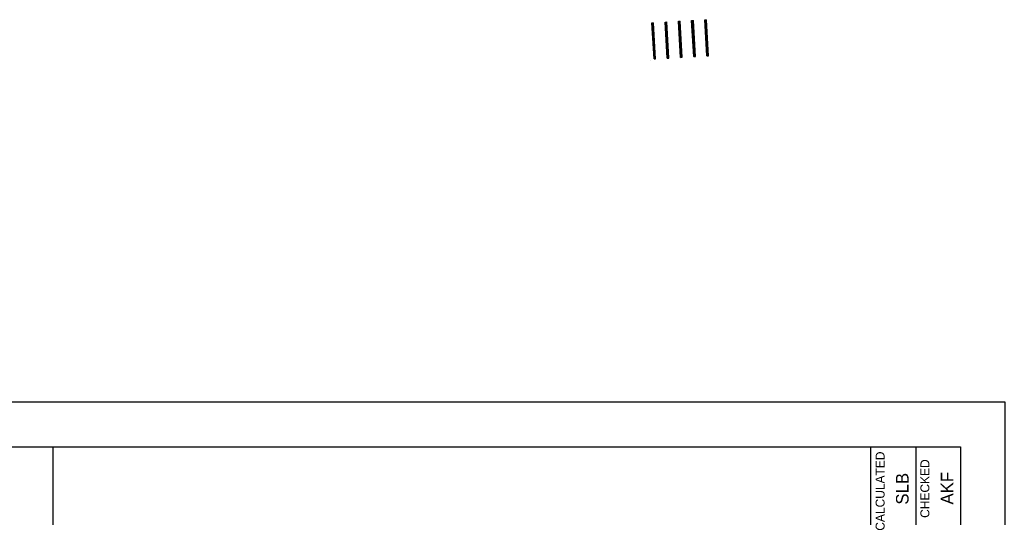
# Model space of a CAD drawing. Extents: x 1822205 to 1824724, y 710141 to 711863.
# Drawn here: x 1823491 to 1824041, y 711177 to 711455 of the extents above; entities that cross this region are included whole.
import ezdxf

# ---------------------------------------------------------------- set-up
doc = ezdxf.new("R2010")
doc.units = 0
for name, color, linetype in [('PM_P_Cells', 7, 'Continuous'), ('SH_Border', 7, 'Continuous'), ('SH_Cut_Line', 7, 'Continuous'), ('SH_Data', 7, 'Continuous')]:
    doc.layers.add(name, color=color, linetype=linetype)

msp = doc.modelspace()

# ---------------------------------------------------------------- linework, layer by layer
at = {"layer": 'PM_P_Cells'}
msp.add_line((1823509.74, 711216.46), (1823509.74, 710166.46), dxfattribs=at)
at = {"layer": 'SH_Border'}
for p, q in [((1823966.39, 710166.46), (1823966.39, 711216.46)), ((1823991.39, 711216.46), (1823991.39, 711166.46))]:
    msp.add_line(p, q, dxfattribs=at)
msp.add_lwpolyline([(1822441.39, 711216.46), (1824016.39, 711216.46), (1824016.39, 710166.46), (1822441.39, 710166.46)], close=True, dxfattribs=at)
at = {"layer": 'SH_Cut_Line'}
msp.add_lwpolyline([(1822341.39, 710141.46), (1824041.39, 710141.46), (1824041.39, 711241.46), (1822341.39, 711241.46)], close=True, dxfattribs=at)
at = {"layer": 'SH_Data'}
for p, q in [((1823844.17, 711453.19), (1823845.07, 711453.24)), ((1823845.3, 711433.06), (1823844.17, 711453.19)), ((1823844.19, 711452.91), (1823845.08, 711452.96)), ((1823846.2, 711433.11), (1823845.07, 711453.24)), ((1823851.5, 711453.6), (1823852.48, 711453.65)), ((1823852.63, 711433.47), (1823851.5, 711453.6)), ((1823851.51, 711453.32), (1823852.49, 711453.37)), ((1823851.53, 711453.04), (1823852.51, 711453.09)), ((1823853.6, 711433.52), (1823852.48, 711453.65)), ((1823858.91, 711454.01), (1823859.89, 711454.07)), ((1823860.03, 711433.88), (1823858.91, 711454.01)), ((1823858.92, 711453.73), (1823859.9, 711453.79)), ((1823858.94, 711453.45), (1823859.92, 711453.51)), ((1823858.95, 711453.17), (1823859.93, 711453.23)), ((1823858.97, 711452.89), (1823859.95, 711452.95)), ((1823861.01, 711433.94), (1823859.89, 711454.07)), ((1823866.32, 711454.43), (1823867.29, 711454.48)), ((1823867.44, 711434.3), (1823866.32, 711454.43)), ((1823866.33, 711454.15), (1823867.31, 711454.2)), ((1823866.35, 711453.87), (1823867.33, 711453.92)), ((1823866.36, 711453.59), (1823867.34, 711453.64)), ((1823866.38, 711453.31), (1823867.36, 711453.36)), ((1823866.39, 711453.03), (1823867.37, 711453.08)), ((1823868.42, 711434.35), (1823867.29, 711454.48)), ((1823873.72, 711454.84), (1823874.62, 711454.89)), ((1823874.85, 711434.71), (1823873.72, 711454.84)), ((1823873.74, 711454.56), (1823874.64, 711454.61)), ((1823873.76, 711454.28), (1823874.65, 711454.33)), ((1823873.77, 711454), (1823874.67, 711454.05)), ((1823873.79, 711453.72), (1823874.69, 711453.77)), ((1823873.8, 711453.44), (1823874.7, 711453.49)), ((1823873.82, 711453.16), (1823874.72, 711453.21)), ((1823873.83, 711452.88), (1823874.73, 711452.93)), ((1823875.75, 711434.76), (1823874.62, 711454.89)), ((1823844.2, 711452.63), (1823845.1, 711452.68)), ((1823844.22, 711452.35), (1823845.12, 711452.4)), ((1823844.23, 711452.07), (1823845.13, 711452.12)), ((1823844.25, 711451.79), (1823845.15, 711451.84)), ((1823844.26, 711451.51), (1823845.16, 711451.56)), ((1823844.28, 711451.23), (1823845.18, 711451.28)), ((1823844.3, 711450.95), (1823845.19, 711451)), ((1823844.31, 711450.67), (1823845.21, 711450.72)), ((1823844.33, 711450.39), (1823845.23, 711450.44)), ((1823844.34, 711450.11), (1823845.24, 711450.16)), ((1823844.36, 711449.83), (1823845.26, 711449.88)), ((1823844.37, 711449.55), (1823845.27, 711449.6)), ((1823844.39, 711449.27), (1823845.29, 711449.32)), ((1823844.41, 711448.99), (1823845.3, 711449.04)), ((1823844.42, 711448.71), (1823845.32, 711448.76)), ((1823844.44, 711448.43), (1823845.34, 711448.48)), ((1823844.45, 711448.15), (1823845.35, 711448.2)), ((1823844.47, 711447.87), (1823845.37, 711447.92)), ((1823844.48, 711447.59), (1823845.38, 711447.64)), ((1823844.5, 711447.31), (1823845.4, 711447.36)), ((1823851.55, 711452.76), (1823852.52, 711452.81)), ((1823851.56, 711452.48), (1823852.54, 711452.53)), ((1823851.58, 711452.2), (1823852.56, 711452.25)), ((1823851.59, 711451.92), (1823852.57, 711451.97)), ((1823851.61, 711451.64), (1823852.59, 711451.69)), ((1823851.62, 711451.36), (1823852.6, 711451.41)), ((1823851.64, 711451.08), (1823852.62, 711451.13)), ((1823851.66, 711450.8), (1823852.63, 711450.85)), ((1823851.67, 711450.52), (1823852.65, 711450.58)), ((1823851.69, 711450.24), (1823852.67, 711450.3)), ((1823851.7, 711449.96), (1823852.68, 711450.02)), ((1823851.72, 711449.68), (1823852.7, 711449.74)), ((1823851.73, 711449.4), (1823852.71, 711449.46)), ((1823851.75, 711449.12), (1823852.73, 711449.18)), ((1823851.77, 711448.84), (1823852.74, 711448.9)), ((1823851.78, 711448.56), (1823852.76, 711448.62)), ((1823851.8, 711448.28), (1823852.77, 711448.34)), ((1823851.81, 711448), (1823852.79, 711448.06)), ((1823851.83, 711447.72), (1823852.81, 711447.78)), ((1823851.84, 711447.45), (1823852.82, 711447.5)), ((1823858.99, 711452.61), (1823859.96, 711452.67)), ((1823859, 711452.33), (1823859.98, 711452.39)), ((1823859.02, 711452.05), (1823860, 711452.11)), ((1823859.03, 711451.77), (1823860.01, 711451.83)), ((1823859.05, 711451.49), (1823860.03, 711451.55)), ((1823859.06, 711451.22), (1823860.04, 711451.27)), ((1823859.08, 711450.94), (1823860.06, 711450.99)), ((1823859.1, 711450.66), (1823860.07, 711450.71)), ((1823859.11, 711450.38), (1823860.09, 711450.43)), ((1823859.13, 711450.1), (1823860.11, 711450.15)), ((1823859.14, 711449.82), (1823860.12, 711449.87)), ((1823859.16, 711449.54), (1823860.14, 711449.59)), ((1823859.17, 711449.26), (1823860.15, 711449.31)), ((1823859.19, 711448.98), (1823860.17, 711449.03)), ((1823859.2, 711448.7), (1823860.18, 711448.75)), ((1823859.22, 711448.42), (1823860.2, 711448.47)), ((1823859.24, 711448.14), (1823860.21, 711448.19)), ((1823859.25, 711447.86), (1823860.23, 711447.92)), ((1823859.27, 711447.58), (1823860.25, 711447.64)), ((1823866.41, 711452.75), (1823867.39, 711452.8)), ((1823866.43, 711452.47), (1823867.4, 711452.52)), ((1823866.44, 711452.19), (1823867.42, 711452.24)), ((1823866.46, 711451.91), (1823867.44, 711451.96)), ((1823866.47, 711451.63), (1823867.45, 711451.68)), ((1823866.49, 711451.35), (1823867.47, 711451.41)), ((1823866.5, 711451.07), (1823867.48, 711451.13)), ((1823866.52, 711450.79), (1823867.5, 711450.85)), ((1823866.53, 711450.51), (1823867.51, 711450.57)), ((1823866.55, 711450.23), (1823867.53, 711450.29)), ((1823866.57, 711449.95), (1823867.54, 711450.01)), ((1823866.58, 711449.67), (1823867.56, 711449.73)), ((1823866.6, 711449.39), (1823867.58, 711449.45)), ((1823866.61, 711449.11), (1823867.59, 711449.17)), ((1823866.63, 711448.83), (1823867.61, 711448.89)), ((1823866.64, 711448.55), (1823867.62, 711448.61)), ((1823866.66, 711448.28), (1823867.64, 711448.33)), ((1823866.68, 711448), (1823867.65, 711448.05)), ((1823866.69, 711447.72), (1823867.67, 711447.77)), ((1823866.71, 711447.44), (1823867.69, 711447.49)), ((1823873.85, 711452.6), (1823874.75, 711452.65)), ((1823873.87, 711452.32), (1823874.76, 711452.37)), ((1823873.88, 711452.05), (1823874.78, 711452.1)), ((1823873.9, 711451.77), (1823874.79, 711451.82)), ((1823873.91, 711451.49), (1823874.81, 711451.54)), ((1823873.93, 711451.21), (1823874.83, 711451.26)), ((1823873.94, 711450.93), (1823874.84, 711450.98)), ((1823873.96, 711450.65), (1823874.86, 711450.7)), ((1823873.97, 711450.37), (1823874.87, 711450.42)), ((1823873.99, 711450.09), (1823874.89, 711450.14)), ((1823874.01, 711449.81), (1823874.9, 711449.86)), ((1823874.02, 711449.53), (1823874.92, 711449.58)), ((1823874.04, 711449.25), (1823874.94, 711449.3)), ((1823874.05, 711448.97), (1823874.95, 711449.02)), ((1823874.07, 711448.69), (1823874.97, 711448.74)), ((1823874.08, 711448.41), (1823874.98, 711448.46)), ((1823874.1, 711448.13), (1823875, 711448.18)), ((1823874.12, 711447.85), (1823875.01, 711447.9)), ((1823874.13, 711447.57), (1823875.03, 711447.62)), ((1823844.51, 711447.03), (1823845.41, 711447.09)), ((1823844.53, 711446.76), (1823845.43, 711446.81)), ((1823844.55, 711446.48), (1823845.44, 711446.53)), ((1823844.56, 711446.2), (1823845.46, 711446.25)), ((1823844.58, 711445.92), (1823845.48, 711445.97)), ((1823844.59, 711445.64), (1823845.49, 711445.69)), ((1823844.61, 711445.36), (1823845.51, 711445.41)), ((1823844.62, 711445.08), (1823845.52, 711445.13)), ((1823844.64, 711444.8), (1823845.54, 711444.85)), ((1823844.66, 711444.52), (1823845.55, 711444.57)), ((1823844.67, 711444.24), (1823845.57, 711444.29)), ((1823844.69, 711443.96), (1823845.59, 711444.01)), ((1823844.7, 711443.68), (1823845.6, 711443.73)), ((1823844.72, 711443.4), (1823845.62, 711443.45)), ((1823844.73, 711443.12), (1823845.63, 711443.17)), ((1823844.75, 711442.84), (1823845.65, 711442.89)), ((1823844.77, 711442.56), (1823845.66, 711442.61)), ((1823844.78, 711442.28), (1823845.68, 711442.33)), ((1823844.8, 711442), (1823845.7, 711442.05)), ((1823851.86, 711447.17), (1823852.84, 711447.22)), ((1823851.87, 711446.89), (1823852.85, 711446.94)), ((1823851.89, 711446.61), (1823852.87, 711446.66)), ((1823851.91, 711446.33), (1823852.88, 711446.38)), ((1823851.92, 711446.05), (1823852.9, 711446.1)), ((1823851.94, 711445.77), (1823852.92, 711445.82)), ((1823851.95, 711445.49), (1823852.93, 711445.54)), ((1823851.97, 711445.21), (1823852.95, 711445.26)), ((1823851.98, 711444.93), (1823852.96, 711444.98)), ((1823852, 711444.65), (1823852.98, 711444.7)), ((1823852.02, 711444.37), (1823852.99, 711444.43)), ((1823852.03, 711444.09), (1823853.01, 711444.15)), ((1823852.05, 711443.81), (1823853.03, 711443.87)), ((1823852.06, 711443.53), (1823853.04, 711443.59)), ((1823852.08, 711443.25), (1823853.06, 711443.31)), ((1823852.09, 711442.97), (1823853.07, 711443.03)), ((1823852.11, 711442.69), (1823853.09, 711442.75)), ((1823852.13, 711442.41), (1823853.1, 711442.47)), ((1823852.14, 711442.13), (1823853.12, 711442.19)), ((1823852.16, 711441.85), (1823853.14, 711441.91)), ((1823859.28, 711447.3), (1823860.26, 711447.36)), ((1823859.3, 711447.02), (1823860.28, 711447.08)), ((1823859.31, 711446.74), (1823860.29, 711446.8)), ((1823859.33, 711446.46), (1823860.31, 711446.52)), ((1823859.35, 711446.18), (1823860.32, 711446.24)), ((1823859.36, 711445.9), (1823860.34, 711445.96)), ((1823859.38, 711445.62), (1823860.36, 711445.68)), ((1823859.39, 711445.34), (1823860.37, 711445.4)), ((1823859.41, 711445.06), (1823860.39, 711445.12)), ((1823859.42, 711444.79), (1823860.4, 711444.84)), ((1823859.44, 711444.51), (1823860.42, 711444.56)), ((1823859.46, 711444.23), (1823860.43, 711444.28)), ((1823859.47, 711443.95), (1823860.45, 711444)), ((1823859.49, 711443.67), (1823860.47, 711443.72)), ((1823859.5, 711443.39), (1823860.48, 711443.44)), ((1823859.52, 711443.11), (1823860.5, 711443.16)), ((1823859.53, 711442.83), (1823860.51, 711442.88)), ((1823859.55, 711442.55), (1823860.53, 711442.6)), ((1823859.57, 711442.27), (1823860.54, 711442.32)), ((1823859.58, 711441.99), (1823860.56, 711442.04)), ((1823866.72, 711447.16), (1823867.7, 711447.21)), ((1823866.74, 711446.88), (1823867.72, 711446.93)), ((1823866.75, 711446.6), (1823867.73, 711446.65)), ((1823866.77, 711446.32), (1823867.75, 711446.37)), ((1823866.79, 711446.04), (1823867.76, 711446.09)), ((1823866.8, 711445.76), (1823867.78, 711445.81)), ((1823866.82, 711445.48), (1823867.8, 711445.53)), ((1823866.83, 711445.2), (1823867.81, 711445.25)), ((1823866.85, 711444.92), (1823867.83, 711444.98)), ((1823866.86, 711444.64), (1823867.84, 711444.7)), ((1823866.88, 711444.36), (1823867.86, 711444.42)), ((1823866.9, 711444.08), (1823867.87, 711444.14)), ((1823866.91, 711443.8), (1823867.89, 711443.86)), ((1823866.93, 711443.52), (1823867.9, 711443.58)), ((1823866.94, 711443.24), (1823867.92, 711443.3)), ((1823866.96, 711442.96), (1823867.94, 711443.02)), ((1823866.97, 711442.68), (1823867.95, 711442.74)), ((1823866.99, 711442.4), (1823867.97, 711442.46)), ((1823867, 711442.12), (1823867.98, 711442.18)), ((1823867.02, 711441.85), (1823868, 711441.9)), ((1823874.15, 711447.29), (1823875.05, 711447.34)), ((1823874.16, 711447.01), (1823875.06, 711447.06)), ((1823874.18, 711446.73), (1823875.08, 711446.78)), ((1823874.19, 711446.45), (1823875.09, 711446.5)), ((1823874.21, 711446.17), (1823875.11, 711446.22)), ((1823874.23, 711445.89), (1823875.12, 711445.94)), ((1823874.24, 711445.62), (1823875.14, 711445.67)), ((1823874.26, 711445.34), (1823875.16, 711445.39)), ((1823874.27, 711445.06), (1823875.17, 711445.11)), ((1823874.29, 711444.78), (1823875.19, 711444.83)), ((1823874.3, 711444.5), (1823875.2, 711444.55)), ((1823874.32, 711444.22), (1823875.22, 711444.27)), ((1823874.33, 711443.94), (1823875.23, 711443.99)), ((1823874.35, 711443.66), (1823875.25, 711443.71)), ((1823874.37, 711443.38), (1823875.26, 711443.43)), ((1823874.38, 711443.1), (1823875.28, 711443.15)), ((1823874.4, 711442.82), (1823875.3, 711442.87)), ((1823874.41, 711442.54), (1823875.31, 711442.59)), ((1823874.43, 711442.26), (1823875.33, 711442.31)), ((1823874.44, 711441.98), (1823875.34, 711442.03)), ((1823844.81, 711441.72), (1823845.71, 711441.77)), ((1823844.83, 711441.44), (1823845.73, 711441.49)), ((1823844.84, 711441.16), (1823845.74, 711441.21)), ((1823844.86, 711440.88), (1823845.76, 711440.93)), ((1823844.88, 711440.6), (1823845.77, 711440.66)), ((1823844.89, 711440.33), (1823845.79, 711440.38)), ((1823844.91, 711440.05), (1823845.81, 711440.1)), ((1823844.92, 711439.77), (1823845.82, 711439.82)), ((1823844.94, 711439.49), (1823845.84, 711439.54)), ((1823844.95, 711439.21), (1823845.85, 711439.26)), ((1823844.97, 711438.93), (1823845.87, 711438.98)), ((1823844.98, 711438.65), (1823845.88, 711438.7)), ((1823845, 711438.37), (1823845.9, 711438.42)), ((1823845.02, 711438.09), (1823845.91, 711438.14)), ((1823845.03, 711437.81), (1823845.93, 711437.86)), ((1823845.05, 711437.53), (1823845.95, 711437.58)), ((1823845.06, 711437.25), (1823845.96, 711437.3)), ((1823845.08, 711436.97), (1823845.98, 711437.02)), ((1823845.09, 711436.69), (1823845.99, 711436.74)), ((1823845.11, 711436.41), (1823846.01, 711436.46)), ((1823852.17, 711441.57), (1823853.15, 711441.63)), ((1823852.19, 711441.3), (1823853.17, 711441.35)), ((1823852.2, 711441.02), (1823853.18, 711441.07)), ((1823852.22, 711440.74), (1823853.2, 711440.79)), ((1823852.23, 711440.46), (1823853.21, 711440.51)), ((1823852.25, 711440.18), (1823853.23, 711440.23)), ((1823852.27, 711439.9), (1823853.24, 711439.95)), ((1823852.28, 711439.62), (1823853.26, 711439.67)), ((1823852.3, 711439.34), (1823853.28, 711439.39)), ((1823852.31, 711439.06), (1823853.29, 711439.11)), ((1823852.33, 711438.78), (1823853.31, 711438.83)), ((1823852.34, 711438.5), (1823853.32, 711438.55)), ((1823852.36, 711438.22), (1823853.34, 711438.27)), ((1823852.38, 711437.94), (1823853.35, 711438)), ((1823852.39, 711437.66), (1823853.37, 711437.72)), ((1823852.41, 711437.38), (1823853.39, 711437.44)), ((1823852.42, 711437.1), (1823853.4, 711437.16)), ((1823852.44, 711436.82), (1823853.42, 711436.88)), ((1823852.45, 711436.54), (1823853.43, 711436.6)), ((1823859.6, 711441.71), (1823860.57, 711441.76)), ((1823859.61, 711441.43), (1823860.59, 711441.49)), ((1823859.63, 711441.15), (1823860.61, 711441.21)), ((1823859.64, 711440.87), (1823860.62, 711440.93)), ((1823859.66, 711440.59), (1823860.64, 711440.65)), ((1823859.67, 711440.31), (1823860.65, 711440.37)), ((1823859.69, 711440.03), (1823860.67, 711440.09)), ((1823859.71, 711439.75), (1823860.68, 711439.81)), ((1823859.72, 711439.47), (1823860.7, 711439.53)), ((1823859.74, 711439.19), (1823860.72, 711439.25)), ((1823859.75, 711438.91), (1823860.73, 711438.97)), ((1823859.77, 711438.63), (1823860.75, 711438.69)), ((1823859.78, 711438.36), (1823860.76, 711438.41)), ((1823859.8, 711438.08), (1823860.78, 711438.13)), ((1823859.82, 711437.8), (1823860.79, 711437.85)), ((1823859.83, 711437.52), (1823860.81, 711437.57)), ((1823859.85, 711437.24), (1823860.83, 711437.29)), ((1823859.86, 711436.96), (1823860.84, 711437.01)), ((1823859.88, 711436.68), (1823860.86, 711436.73)), ((1823859.89, 711436.4), (1823860.87, 711436.45)), ((1823867.04, 711441.57), (1823868.01, 711441.62)), ((1823867.05, 711441.29), (1823868.03, 711441.34)), ((1823867.07, 711441.01), (1823868.05, 711441.06)), ((1823867.08, 711440.73), (1823868.06, 711440.78)), ((1823867.1, 711440.45), (1823868.08, 711440.5)), ((1823867.11, 711440.17), (1823868.09, 711440.22)), ((1823867.13, 711439.89), (1823868.11, 711439.94)), ((1823867.15, 711439.61), (1823868.12, 711439.66)), ((1823867.16, 711439.33), (1823868.14, 711439.38)), ((1823867.18, 711439.05), (1823868.16, 711439.1)), ((1823867.19, 711438.77), (1823868.17, 711438.83)), ((1823867.21, 711438.49), (1823868.19, 711438.55)), ((1823867.22, 711438.21), (1823868.2, 711438.27)), ((1823867.24, 711437.93), (1823868.22, 711437.99)), ((1823867.26, 711437.65), (1823868.23, 711437.71)), ((1823867.27, 711437.37), (1823868.25, 711437.43)), ((1823867.29, 711437.09), (1823868.27, 711437.15)), ((1823867.3, 711436.81), (1823868.28, 711436.87)), ((1823867.32, 711436.53), (1823868.3, 711436.59)), ((1823874.46, 711441.7), (1823875.36, 711441.75)), ((1823874.48, 711441.42), (1823875.37, 711441.47)), ((1823874.49, 711441.14), (1823875.39, 711441.19)), ((1823874.51, 711440.86), (1823875.41, 711440.91)), ((1823874.52, 711440.58), (1823875.42, 711440.63)), ((1823874.54, 711440.3), (1823875.44, 711440.35)), ((1823874.55, 711440.02), (1823875.45, 711440.07)), ((1823874.57, 711439.74), (1823875.47, 711439.79)), ((1823874.59, 711439.46), (1823875.48, 711439.52)), ((1823874.6, 711439.19), (1823875.5, 711439.24)), ((1823874.62, 711438.91), (1823875.52, 711438.96)), ((1823874.63, 711438.63), (1823875.53, 711438.68)), ((1823874.65, 711438.35), (1823875.55, 711438.4)), ((1823874.66, 711438.07), (1823875.56, 711438.12)), ((1823874.68, 711437.79), (1823875.58, 711437.84)), ((1823874.7, 711437.51), (1823875.59, 711437.56)), ((1823874.71, 711437.23), (1823875.61, 711437.28)), ((1823874.73, 711436.95), (1823875.62, 711437)), ((1823874.74, 711436.67), (1823875.64, 711436.72)), ((1823874.76, 711436.39), (1823875.66, 711436.44)), ((1823843.36, 711431.97), (1823843.36, 711431.97)), ((1823845.13, 711436.13), (1823846.02, 711436.18)), ((1823845.14, 711435.85), (1823846.04, 711435.9)), ((1823845.16, 711435.57), (1823846.06, 711435.62)), ((1823845.17, 711435.29), (1823846.07, 711435.34)), ((1823845.19, 711435.01), (1823846.09, 711435.06)), ((1823845.2, 711434.73), (1823846.1, 711434.78)), ((1823845.22, 711434.45), (1823846.12, 711434.5)), ((1823845.24, 711434.18), (1823846.13, 711434.23)), ((1823845.25, 711433.9), (1823846.15, 711433.95)), ((1823845.27, 711433.62), (1823846.17, 711433.67)), ((1823845.28, 711433.34), (1823846.18, 711433.39)), ((1823845.3, 711433.06), (1823846.2, 711433.11)), ((1823852.47, 711436.26), (1823853.45, 711436.32)), ((1823852.49, 711435.98), (1823853.46, 711436.04)), ((1823852.5, 711435.7), (1823853.48, 711435.76)), ((1823852.52, 711435.42), (1823853.5, 711435.48)), ((1823852.53, 711435.14), (1823853.51, 711435.2)), ((1823852.55, 711434.87), (1823853.53, 711434.92)), ((1823852.56, 711434.59), (1823853.54, 711434.64)), ((1823852.58, 711434.31), (1823853.56, 711434.36)), ((1823852.6, 711434.03), (1823853.57, 711434.08)), ((1823852.61, 711433.75), (1823853.59, 711433.8)), ((1823852.63, 711433.47), (1823853.6, 711433.52)), ((1823859.91, 711436.12), (1823860.89, 711436.17)), ((1823859.93, 711435.84), (1823860.9, 711435.89)), ((1823859.94, 711435.56), (1823860.92, 711435.61)), ((1823859.96, 711435.28), (1823860.93, 711435.33)), ((1823859.97, 711435), (1823860.95, 711435.06)), ((1823859.99, 711434.72), (1823860.97, 711434.78)), ((1823860, 711434.44), (1823860.98, 711434.5)), ((1823860.02, 711434.16), (1823861, 711434.22)), ((1823860.03, 711433.88), (1823861.01, 711433.94)), ((1823867.33, 711436.25), (1823868.31, 711436.31)), ((1823867.35, 711435.97), (1823868.33, 711436.03)), ((1823867.36, 711435.7), (1823868.34, 711435.75)), ((1823867.38, 711435.42), (1823868.36, 711435.47)), ((1823867.4, 711435.14), (1823868.37, 711435.19)), ((1823867.41, 711434.86), (1823868.39, 711434.91)), ((1823867.43, 711434.58), (1823868.41, 711434.63)), ((1823867.44, 711434.3), (1823868.42, 711434.35)), ((1823874.77, 711436.11), (1823875.67, 711436.16)), ((1823874.79, 711435.83), (1823875.69, 711435.88)), ((1823874.8, 711435.55), (1823875.7, 711435.6)), ((1823874.82, 711435.27), (1823875.72, 711435.32)), ((1823874.84, 711434.99), (1823875.73, 711435.04)), ((1823874.85, 711434.71), (1823875.75, 711434.76))]:
    msp.add_line(p, q, dxfattribs=at)

# ---------------------------------------------------------------- texts
for s, height, p in [('CALCULATED', 5, (1823974.01, 711169.68)), ('CHECKED', 5, (1823999.01, 711176.85)), ('SLB', 7, (1823987.39, 711184.26)), ('AKF', 7, (1824012.39, 711184.31))]:
    msp.add_text(s, height=height, rotation=90, dxfattribs=at).set_placement(p)

doc.saveas('drawing.dxf')
